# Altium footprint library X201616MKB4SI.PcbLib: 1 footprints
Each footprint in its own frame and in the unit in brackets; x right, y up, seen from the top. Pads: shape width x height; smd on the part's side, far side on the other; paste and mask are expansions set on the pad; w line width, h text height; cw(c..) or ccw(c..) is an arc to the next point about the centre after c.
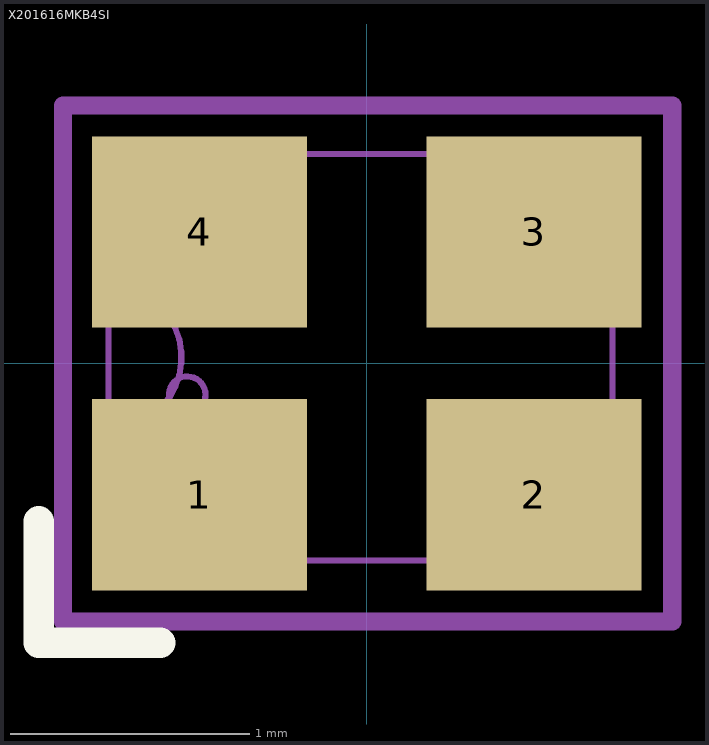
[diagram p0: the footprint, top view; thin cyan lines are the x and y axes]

## X201616MKB4SI [mm]
pads (4):
  rect 0.9x0.8 smd paste+0 mask+0: 1(-0.7,-0.55) 2(0.7,-0.55) 3(0.7,0.55) 4(-0.7,0.55)
Top Overlay:
  lines w0.127: -1.372,-0.66 -1.372,-1.168 -0.864,-1.168
Mechanical 13:
  circle w0.025: c-0.75,-0.131 r0.076
  lines w0.025: -1.079,-0.279 ccw(c-1.079,0.025) -1.079,0.33 ; -1.079,-0.826 1.029,-0.826 1.029,0.876 -1.079,0.876 -1.079,-0.826
Mechanical 15:
  lines w0.076: -1.27,-1.079 1.234,-1.079 1.279,-1.079 1.279,1.08 -1.27,1.08 -1.27,-1.079
3D body "SMD4_FA-128_2P0X1P6_SEC.step": height 0.51, standoff 0, extent -1.079,-0.826 1.029,0.876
